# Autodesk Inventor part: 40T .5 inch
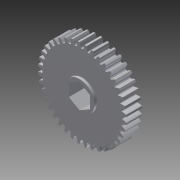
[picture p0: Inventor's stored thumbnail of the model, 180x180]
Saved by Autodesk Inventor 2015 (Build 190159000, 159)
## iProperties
Created: 2014-11
Part Number: 40T .5 inch
Material: Aluminum 6061
Document SubType Name: Modeling
Designer: Michael
Density: 2.71 g/cm^3
Appearance: Aluminum - Flat
Author: svradm
Title: 217-2708.20121204.STEP
Organization: Microsoft
Description: STEP AP203
Creation Date: 2012-12-05
Sending System: SolidWorks 2012
Preprocessor: SwSTEP 2.0
Author: Michael
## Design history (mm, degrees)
node "40T .5 inch1"
node "Combine1"
node "Base1"
